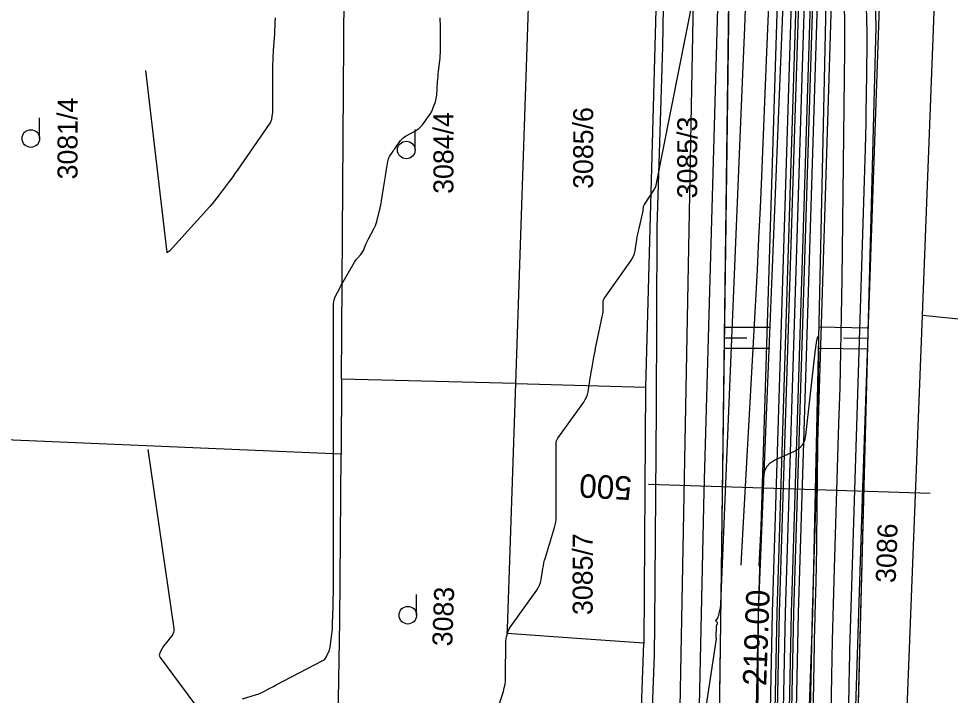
# Model space of a CAD drawing. Extents: x -534410 to -534262, y -1190162 to -1189584.
# Drawn here: x -534356.09 to -534316.44, y -1190081.68 to -1190052.88 of the extents above; entities that cross this region are included whole.
import ezdxf

# ---------------------------------------------------------------- set-up
doc = ezdxf.new("R2010")
doc.units = 0
for name, color, linetype in [('07_ELEKTRO', 7, 'Continuous'), ('30', 7, 'Continuous'), ('31', 7, 'Continuous'), ('40', 7, 'Continuous'), ('_linie', 7, 'Continuous'), ('_N_osa', 7, 'Continuous'), ('_N_tenká', 7, 'Continuous'), ('_N_tenká_velmi', 7, 'Continuous'), ('_N_text', 7, 'Continuous'), ('_přístup', 7, 'Continuous'), ('_tenka', 7, 'Continuous'), ('_velmi_tenka', 7, 'Continuous'), ('Default', 7, 'Continuous'), ('Hranice parcel', 7, 'Continuous'), ('Parcelní čísla', 7, 'Continuous'), ('Značky kultur', 7, 'Continuous')]:
    doc.layers.add(name, color=color, linetype=linetype)

msp = doc.modelspace()

# ---------------------------------------------------------------- linework, layer by layer
at = {"layer": '07_ELEKTRO'}
msp.add_lwpolyline([(-534329.31, -1190087.46), (-534329.03, -1190079.95), (-534329.01, -1190078.66), (-534328.95, -1190069.47), (-534328.91, -1190061.75), (-534328.68, -1190054.09), (-534328.55, -1190046.44), (-534328.261, -1190025.497), (-534332.174, -1190007.081), (-534334.321, -1190004.167), (-534336.852, -1190002.737), (-534339.713, -1190001.803)], dxfattribs=at)
at = {"layer": '30'}
for points in [[(-534321.439, -1190024.07), (-534321.403, -1190024.729), (-534321.16, -1190031.821), (-534321.095, -1190033.569), (-534321.018, -1190035.317), (-534320.93, -1190037.065), (-534320.831, -1190038.812), (-534320.052, -1190051.814), (-534320.024, -1190052.363), (-534320.005, -1190052.912), (-534319.997, -1190053.461), (-534319.998, -1190054.011), (-534320.024, -1190056.21), (-534320.031, -1190056.76), (-534320.042, -1190057.31), (-534320.054, -1190057.86), (-534320.07, -1190058.409), (-534320.726, -1190079.747), (-534320.736, -1190080.069), (-534320.744, -1190080.391), (-534320.751, -1190080.713), (-534320.757, -1190081.035), (-534320.78, -1190082.323)], [(-534328.187, -1190091.169), (-534326.393, -1190079.271), (-534326.393, -1190079.267), (-534326.393, -1190079.263), (-534326.394, -1190079.26), (-534326.395, -1190079.256), (-534326.4, -1190079.241), (-534326.401, -1190079.237), (-534326.402, -1190079.234), (-534326.402, -1190079.23), (-534326.403, -1190079.226), (-534326.385, -1190078.709), (-534326.384, -1190078.703), (-534326.383, -1190078.696), (-534326.381, -1190078.69), (-534326.378, -1190078.684), (-534326.357, -1190078.649), (-534326.355, -1190078.646), (-534326.343, -1190078.602), (-534326.342, -1190078.595), (-534326.343, -1190078.588), (-534326.346, -1190078.582), (-534326.35, -1190078.577), (-534326.405, -1190078.527), (-534326.413, -1190078.517), (-534326.416, -1190078.506), (-534326.414, -1190078.495), (-534326.407, -1190078.484), (-534326.342, -1190078.407), (-534326.34, -1190078.403), (-534326.338, -1190078.4), (-534326.336, -1190078.396), (-534326.335, -1190078.392), (-534326.33, -1190078.372), (-534326.327, -1190078.361), (-534326.321, -1190078.34), (-534326.318, -1190078.33), (-534326.314, -1190078.321), (-534326.301, -1190078.29), (-534326.298, -1190078.283), (-534326.296, -1190078.275), (-534326.291, -1190078.255), (-534326.288, -1190078.243), (-534326.278, -1190078.211), (-534326.276, -1190078.204), (-534326.274, -1190078.197), (-534326.273, -1190078.19), (-534326.271, -1190078.183), (-534326.227, -1190077.952), (-534326.22, -1190077.911), (-534326.214, -1190077.87), (-534326.21, -1190077.829), (-534326.208, -1190077.787), (-534325.27, -1190055.236), (-534325.189, -1190053.257), (-534325.109, -1190051.279)], [(-534346.562, -1190081.825), (-534345.87, -1190081.605), (-534345.807, -1190081.583), (-534345.746, -1190081.559), (-534345.685, -1190081.531), (-534345.626, -1190081.501), (-534345.393, -1190081.375), (-534345.335, -1190081.343), (-534345.276, -1190081.312), (-534345.217, -1190081.281), (-534345.159, -1190081.25), (-534343.147, -1190080.2), (-534343.099, -1190080.171), (-534343.059, -1190080.135), (-534343.024, -1190080.093), (-534342.997, -1190080.045), (-534342.898, -1190079.841), (-534342.875, -1190079.79), (-534342.857, -1190079.737), (-534342.843, -1190079.682), (-534342.834, -1190079.627), (-534342.762, -1190079.068), (-534342.749, -1190078.956), (-534342.739, -1190078.844), (-534342.732, -1190078.732), (-534342.727, -1190078.619), (-534342.708, -1190077.898), (-534342.708, -1190077.88), (-534342.708, -1190077.862), (-534342.708, -1190077.827), (-534342.707, -1190077.809), (-534342.707, -1190077.791), (-534342.689, -1190077.086), (-534342.687, -1190076.965), (-534342.685, -1190076.844), (-534342.683, -1190076.724), (-534342.683, -1190076.603), (-534342.683, -1190065.019), (-534342.678, -1190064.933), (-534342.663, -1190064.849), (-534342.638, -1190064.769), (-534342.602, -1190064.69), (-534342.44, -1190064.382), (-534342.4, -1190064.305), (-534342.358, -1190064.229), (-534342.316, -1190064.153), (-534342.273, -1190064.077), (-534341.796, -1190063.249), (-534341.768, -1190063.204), (-534341.738, -1190063.161), (-534341.706, -1190063.119), (-534341.671, -1190063.079), (-534341.528, -1190062.923), (-534341.494, -1190062.882), (-534341.464, -1190062.839), (-534341.439, -1190062.794), (-534341.417, -1190062.746), (-534341.309, -1190062.482), (-534341.284, -1190062.423), (-534341.257, -1190062.363), (-534341.228, -1190062.305), (-534341.198, -1190062.248), (-534340.985, -1190061.861), (-534340.942, -1190061.777), (-534340.904, -1190061.69), (-534340.873, -1190061.601), (-534340.847, -1190061.51), (-534340.732, -1190061.043), (-534340.709, -1190060.944), (-534340.687, -1190060.844), (-534340.668, -1190060.743), (-534340.65, -1190060.642), (-534340.562, -1190060.092), (-534340.534, -1190059.922), (-534340.479, -1190059.581), (-534340.461, -1190059.467), (-534340.379, -1190058.955), (-534340.367, -1190058.901), (-534340.35, -1190058.849), (-534340.328, -1190058.799), (-534340.3, -1190058.751), (-534340.178, -1190058.564), (-534340.147, -1190058.518), (-534340.116, -1190058.471), (-534340.084, -1190058.425), (-534340.052, -1190058.38), (-534339.837, -1190058.075), (-534339.787, -1190058.012), (-534339.731, -1190057.957), (-534339.668, -1190057.908), (-534339.6, -1190057.867), (-534339.204, -1190057.658), (-534339.118, -1190057.606), (-534339.039, -1190057.546), (-534338.969, -1190057.477), (-534338.905, -1190057.399), (-534338.593, -1190056.966), (-534338.551, -1190056.904), (-534338.515, -1190056.84), (-534338.483, -1190056.773), (-534338.456, -1190056.704), (-534338.356, -1190056.422), (-534338.334, -1190056.351), (-534338.316, -1190056.279), (-534338.304, -1190056.206), (-534338.296, -1190056.133), (-534338.259, -1190055.571), (-534338.251, -1190055.459), (-534338.241, -1190055.346), (-534338.231, -1190055.234), (-534338.218, -1190055.121), (-534338.166, -1190054.672), (-534338.154, -1190054.56), (-534338.146, -1190054.447), (-534338.141, -1190054.335), (-534338.14, -1190054.222), (-534338.14, -1190053.34), (-534338.14, -1190053.291), (-534338.141, -1190053.241), (-534338.141, -1190053.192), (-534338.143, -1190053.142), (-534338.148, -1190052.943), (-534338.149, -1190052.894), (-534338.15, -1190052.845)], [(-534324.582, -1190076.169), (-534324.371, -1190072.338), (-534324.333, -1190072.121), (-534324.245, -1190071.938), (-534324.108, -1190071.789), (-534323.919, -1190071.675), (-534323.067, -1190071.284), (-534322.878, -1190071.169), (-534322.734, -1190071.02), (-534322.638, -1190070.838), (-534322.588, -1190070.622), (-534322.186, -1190067.078), (-534322.121, -1190066.577), (-534322.076, -1190066.412), (-534322.053, -1190066.582), (-534322.05, -1190067.087), (-534322.157, -1190076.409), (-534322.16, -1190076.598), (-534322.163, -1190076.787), (-534322.168, -1190076.975), (-534322.173, -1190077.164), (-534322.196, -1190077.919), (-534322.202, -1190078.108), (-534322.206, -1190078.297), (-534322.211, -1190078.485), (-534322.214, -1190078.674), (-534322.64, -1190103.1)], [(-534350.597, -1190071.215), (-534349.487, -1190078.826), (-534349.483, -1190078.915), (-534349.496, -1190078.999), (-534349.528, -1190079.078), (-534349.577, -1190079.152), (-534349.858, -1190079.496), (-534349.892, -1190079.539), (-534349.923, -1190079.584), (-534349.952, -1190079.631), (-534349.979, -1190079.679), (-534350.082, -1190079.873), (-534350.1, -1190079.921), (-534350.104, -1190079.968), (-534350.093, -1190080.014), (-534350.068, -1190080.059), (-534348.04, -1190082.803)]]:
    msp.add_lwpolyline(points, dxfattribs=at)
at = {"layer": '31'}
for points in [[(-534335.714, -1190082.285), (-534335.462, -1190081.509), (-534335.421, -1190081.363), (-534335.391, -1190081.216), (-534335.372, -1190081.066), (-534335.365, -1190080.915), (-534335.35, -1190079.342), (-534335.348, -1190079.29), (-534335.341, -1190079.24), (-534335.331, -1190079.189), (-534335.316, -1190079.14), (-534335.25, -1190078.943), (-534335.231, -1190078.895), (-534335.21, -1190078.848), (-534335.184, -1190078.803), (-534335.156, -1190078.76), (-534334.039, -1190077.197), (-534333.975, -1190077.095), (-534333.923, -1190076.988), (-534333.885, -1190076.877), (-534333.859, -1190076.759), (-534333.782, -1190076.28), (-534333.76, -1190076.161), (-534333.735, -1190076.042), (-534333.705, -1190075.925), (-534333.672, -1190075.808), (-534333.283, -1190074.54), (-534333.253, -1190074.427), (-534333.231, -1190074.313), (-534333.218, -1190074.197), (-534333.214, -1190074.08), (-534333.214, -1190073.506), (-534333.214, -1190073.374), (-534333.214, -1190073.241), (-534333.214, -1190072.977), (-534333.214, -1190072.911), (-534333.214, -1190072.845), (-534333.214, -1190072.778), (-534333.214, -1190072.712), (-534333.214, -1190072.448), (-534333.214, -1190072.315), (-534333.214, -1190072.183), (-534333.214, -1190071.506), (-534333.214, -1190071.374), (-534333.214, -1190071.241), (-534333.214, -1190070.977), (-534333.21, -1190070.912), (-534333.195, -1190070.851), (-534333.171, -1190070.792), (-534333.138, -1190070.737), (-534332.038, -1190069.196), (-534331.974, -1190069.095), (-534331.923, -1190068.989), (-534331.885, -1190068.877), (-534331.859, -1190068.76), (-534331.782, -1190068.282), (-534331.762, -1190068.162), (-534331.742, -1190068.043), (-534331.721, -1190067.924), (-534331.7, -1190067.804), (-534331.607, -1190067.281), (-534331.583, -1190067.154), (-534331.559, -1190067.027), (-534331.534, -1190066.9), (-534331.508, -1190066.774), (-534331.24, -1190065.505), (-534331.228, -1190065.439), (-534331.22, -1190065.374), (-534331.214, -1190065.308), (-534331.213, -1190065.242), (-534331.213, -1190064.977), (-534331.208, -1190064.912), (-534331.193, -1190064.851), (-534331.169, -1190064.792), (-534331.135, -1190064.737), (-534330.037, -1190063.195), (-534329.974, -1190063.094), (-534329.923, -1190062.988), (-534329.884, -1190062.877), (-534329.859, -1190062.76), (-534329.782, -1190062.284), (-534329.761, -1190062.165), (-534329.739, -1190062.047), (-534329.715, -1190061.928), (-534329.688, -1190061.811), (-534329.528, -1190061.128), (-534329.522, -1190061.1), (-534329.517, -1190061.072), (-534329.512, -1190061.044), (-534329.509, -1190061.016), (-534329.497, -1190060.902), (-534329.493, -1190060.874), (-534329.485, -1190060.847), (-534329.474, -1190060.821), (-534329.46, -1190060.796), (-534329.033, -1190060.14), (-534329.011, -1190060.107), (-534328.99, -1190060.074), (-534328.985, -1190060.065), (-534328.981, -1190060.057), (-534328.977, -1190060.047), (-534328.975, -1190060.038), (-534327.353, -1190051.869)], [(-534325.339, -1190076.14), (-534325.297, -1190075.335), (-534324.723, -1190064.883), (-534324.653, -1190063.563), (-534324.587, -1190062.243), (-534324.526, -1190060.922), (-534324.469, -1190059.601), (-534324.249, -1190054.317), (-534324.195, -1190052.996), (-534324.141, -1190051.675)], [(-534320.964, -1190052.178), (-534320.949, -1190053.183), (-534320.951, -1190054.188), (-534321.064, -1190063.973), (-534321.085, -1190065.511), (-534321.114, -1190067.048), (-534321.15, -1190068.585), (-534321.193, -1190070.122), (-534321.382, -1190076.27), (-534321.427, -1190077.807), (-534321.467, -1190079.344), (-534321.501, -1190080.881), (-534321.531, -1190082.418)], [(-534345.17, -1190052.846), (-534345.178, -1190052.913), (-534345.183, -1190052.981), (-534345.192, -1190053.254), (-534345.195, -1190053.323), (-534345.198, -1190053.391), (-534345.202, -1190053.459), (-534345.206, -1190053.527), (-534345.256, -1190054.246), (-534345.26, -1190054.306), (-534345.263, -1190054.366), (-534345.266, -1190054.426), (-534345.269, -1190054.485), (-534345.277, -1190054.725), (-534345.279, -1190054.785), (-534345.281, -1190054.845), (-534345.281, -1190054.904), (-534345.282, -1190054.964), (-534345.282, -1190056.743), (-534345.283, -1190056.794), (-534345.285, -1190056.844), (-534345.29, -1190056.895), (-534345.296, -1190056.945), (-534345.325, -1190057.147), (-534345.335, -1190057.196), (-534345.351, -1190057.243), (-534345.372, -1190057.288), (-534345.398, -1190057.331), (-534346.793, -1190059.347), (-534346.885, -1190059.479), (-534346.978, -1190059.61), (-534347.072, -1190059.741), (-534347.168, -1190059.87), (-534347.551, -1190060.387), (-534347.649, -1190060.515), (-534347.749, -1190060.64), (-534347.853, -1190060.763), (-534347.959, -1190060.883), (-534349.675, -1190062.776), (-534349.681, -1190062.782), (-534349.687, -1190062.787), (-534349.694, -1190062.792), (-534349.701, -1190062.796), (-534349.74, -1190062.82), (-534349.746, -1190062.824), (-534349.754, -1190062.831), (-534349.757, -1190062.835), (-534349.761, -1190062.843), (-534349.762, -1190062.842), (-534349.762, -1190062.841), (-534350.673, -1190055.087)]]:
    msp.add_lwpolyline(points, dxfattribs=at)
at = {"layer": '_linie'}
for points in [[(-534351.8, -1189951.99), (-534346.88, -1189964.25), (-534328.11, -1190005.55), (-534325.796, -1190021.686), (-534325.86, -1190050.97), (-534326.22, -1190078.56), (-534326.79, -1190120.4), (-534329.12, -1190134.93), (-534323.49, -1190133.89), (-534321.38, -1190121.46), (-534319.59, -1190053.22), (-534320.45, -1190021.195), (-534322.75, -1190003.33), (-534340.65, -1189960.04), (-534344.52, -1189948.89)], [(-534347.45, -1189950.137), (-534345.54, -1189954.54), (-534325.02, -1190005.35), (-534322.054, -1190021.393), (-534321.72, -1190051.56), (-534322.31, -1190078.15), (-534323.81, -1190120.37), (-534326.521, -1190134.45)], [(-534328.194, -1190134.759), (-534324.85, -1190120.45), (-534324.6, -1190078.17), (-534323.54, -1190051.92), (-534323.273, -1190021.516), (-534325.81, -1190005.43), (-534346.66, -1189954.59), (-534348.342, -1189950.518)]]:
    msp.add_lwpolyline(points, dxfattribs=at)
at = {"layer": '_N_osa'}
msp.add_lwpolyline([(-534327.357, -1190134.604), (-534324.33, -1190120.41), (-534323.455, -1190078.16), (-534322.63, -1190051.74), (-534322.663, -1190021.455), (-534325.415, -1190005.39), (-534346.1, -1189954.565), (-534347.892, -1189950.326)], dxfattribs=at)
at = {"layer": '_N_tenká'}
for points in [[(-534326.133, -1190134.378), (-534323.183, -1190120.543), (-534322.305, -1190078.19), (-534321.48, -1190051.757), (-534321.513, -1190021.356), (-534324.303, -1190005.072), (-534345.038, -1189954.124), (-534346.832, -1189949.878)], [(-534327.091, -1190134.555), (-534324.081, -1190120.439), (-534323.205, -1190078.166), (-534322.38, -1190051.744), (-534322.413, -1190021.433), (-534325.173, -1190005.321), (-534345.869, -1189954.469), (-534347.661, -1189950.228)], [(-534328.581, -1190134.83), (-534325.477, -1190120.277), (-534324.605, -1190078.13), (-534323.78, -1190051.723), (-534323.813, -1190021.553), (-534326.527, -1190005.708), (-534347.162, -1189955.006), (-534348.951, -1189950.773)], [(-534327.623, -1190134.654), (-534324.579, -1190120.381), (-534323.705, -1190078.154), (-534322.88, -1190051.736), (-534322.913, -1190021.476), (-534325.657, -1190005.459), (-534346.331, -1189954.661), (-534348.122, -1189950.423)]]:
    msp.add_lwpolyline(points, dxfattribs=at)
at = {"layer": '_N_tenká_velmi'}
for points in [[(-534326.985, -1190134.536), (-534323.981, -1190120.45), (-534323.105, -1190078.169), (-534322.28, -1190051.745), (-534322.313, -1190021.425), (-534325.076, -1190005.293), (-534345.777, -1189954.431), (-534347.569, -1189950.189)], [(-534326.772, -1190134.496), (-534323.781, -1190120.474), (-534322.905, -1190078.174), (-534322.08, -1190051.748), (-534322.113, -1190021.407), (-534324.883, -1190005.238), (-534345.592, -1189954.354), (-534347.385, -1189950.112)], [(-534327.943, -1190134.713), (-534324.879, -1190120.346), (-534324.005, -1190078.146), (-534323.18, -1190051.732), (-534323.213, -1190021.502), (-534325.947, -1190005.542), (-534346.608, -1189954.776), (-534348.398, -1189950.54)], [(-534327.73, -1190134.673), (-534324.679, -1190120.37), (-534323.805, -1190078.151), (-534322.98, -1190051.735), (-534323.013, -1190021.485), (-534325.754, -1190005.487), (-534346.423, -1189954.699), (-534348.214, -1189950.462)]]:
    msp.add_lwpolyline(points, dxfattribs=at)
at = {"layer": '_N_text'}
msp.add_lwpolyline([(-534317.294, -1190073.085), (-534329.288, -1190072.711)], dxfattribs=at)
at = {"layer": '_přístup'}
msp.add_lwpolyline([(-534330.552, -1190135.191), (-534328.648, -1190119.819), (-534326.845, -1190024.247), (-534332.805, -1189999.297), (-534354.454, -1189948.317)], dxfattribs=at)
at = {"layer": '_tenka'}
for points in [[(-534351.8, -1189951.99), (-534346.88, -1189964.25), (-534328.11, -1190005.55), (-534325.796, -1190021.686), (-534325.86, -1190050.97), (-534326.22, -1190078.56), (-534326.79, -1190120.4), (-534329.12, -1190134.93), (-534323.49, -1190133.89), (-534321.38, -1190121.46), (-534319.59, -1190053.22), (-534320.45, -1190021.195), (-534322.75, -1190003.33), (-534340.65, -1189960.04), (-534344.52, -1189948.89)], [(-534327.55, -1190134.64), (-534323.49, -1190133.89), (-534321.38, -1190121.46), (-534319.59, -1190053.22), (-534320.45, -1190021.195), (-534322.75, -1190003.33), (-534340.65, -1189960.04), (-534344.52, -1189948.89)], [(-534347.45, -1189950.137), (-534345.54, -1189954.54), (-534325.02, -1190005.35), (-534322.054, -1190021.393), (-534321.72, -1190051.56), (-534322.31, -1190078.15), (-534323.81, -1190120.37), (-534326.521, -1190134.45)], [(-534347.45, -1189950.137), (-534345.54, -1189954.54), (-534325.02, -1190005.35), (-534322.054, -1190021.393), (-534321.72, -1190051.56), (-534322.31, -1190078.15), (-534323.81, -1190120.37), (-534326.521, -1190134.45)], [(-534328.194, -1190134.759), (-534324.85, -1190120.45), (-534324.6, -1190078.17), (-534323.54, -1190051.92), (-534323.273, -1190021.516), (-534325.81, -1190005.43), (-534346.66, -1189954.59), (-534348.342, -1189950.518)], [(-534328.194, -1190134.759), (-534324.85, -1190120.45), (-534324.6, -1190078.17), (-534323.54, -1190051.92), (-534323.273, -1190021.516), (-534325.81, -1190005.43), (-534346.66, -1189954.59), (-534348.342, -1189950.518)], [(-534351.8, -1189951.99), (-534346.88, -1189964.25), (-534328.11, -1190005.55), (-534325.796, -1190021.686), (-534325.86, -1190050.97), (-534326.22, -1190078.56), (-534326.79, -1190120.4), (-534329.12, -1190134.93), (-534327.55, -1190134.64)]]:
    msp.add_lwpolyline(points, dxfattribs=at)
at = {"layer": '_velmi_tenka'}
for p, q in [((-534326.063, -1190066.011), (-534324.128, -1190066.008)), ((-534319.931, -1190066.048), (-534322.043, -1190066.012)), ((-534326.062, -1190066.461), (-534325.095, -1190066.459)), ((-534319.938, -1190066.498), (-534320.994, -1190066.48)), ((-534326.061, -1190066.911), (-534324.126, -1190066.908)), ((-534319.946, -1190066.948), (-534322.058, -1190066.912))]:
    msp.add_line(p, q, dxfattribs=at)
at = {"layer": 'Default'}
for p, q in [((-534325.86, -1190050.97), (-534326.22, -1190078.56)), ((-534321.38, -1190121.46), (-534319.59, -1190053.22)), ((-534326.22, -1190078.56), (-534326.79, -1190120.4))]:
    msp.add_line(p, q, dxfattribs=at)
msp.add_lwpolyline([(-534319.59, -1190053.22), (-534320.45, -1190021.195), (-534322.75, -1190003.33)], dxfattribs=at)
at = {"layer": 'Hranice parcel'}
for p, q in [((-534334.93, -1190068.41), (-534334.16, -1190045.57)), ((-534328.79, -1190045.66), (-534329.41, -1190068.56)), ((-534318.39, -1190085.1), (-534317.63, -1190065.52)), ((-534307.49, -1190066.49), (-534317.63, -1190065.52)), ((-534342.35, -1190068.22), (-534342.37, -1190071.42)), ((-534334.93, -1190068.41), (-534342.35, -1190068.22)), ((-534334.93, -1190068.41), (-534329.41, -1190068.56)), ((-534329.41, -1190068.56), (-534329.49, -1190079.46)), ((-534342.37, -1190071.42), (-534367.49, -1190070.35)), ((-534329.74, -1190087.07), (-534329.49, -1190079.46))]:
    msp.add_line(p, q, dxfattribs=at)
for points in [[(-534333.99, -1189993.03), (-534331.98, -1189997.67), (-534327.34, -1190013.08), (-534325.48, -1190021.81), (-534326.93, -1190073), (-534328.13, -1190128.3), (-534328.71, -1190131.86)], [(-534322.11, -1190134.26), (-534321.95, -1190128.7), (-534320.16, -1190072.85), (-534318.8, -1190033.53)], [(-534317.63, -1190065.52), (-534317.11, -1190052.22), (-534318.8, -1190033.53)], [(-534342.35, -1190068.22), (-534342.22, -1190049.76), (-534342.19, -1190045.44)], [(-534329.49, -1190079.46), (-534332.14, -1190079.27), (-534335.3, -1190079.04), (-534335.29, -1190078.85), (-534334.93, -1190068.41)], [(-534342.57, -1190087.3), (-534342.5, -1190083.48), (-534342.42, -1190078.52), (-534342.37, -1190071.42)]]:
    msp.add_lwpolyline(points, dxfattribs=at)
at = {"layer": 'Značky kultur'}
for p, q in [((-534355.195, -1190057.985), (-534355.195, -1190057.11)), ((-534339.217, -1190058.472), (-534339.217, -1190057.597)), ((-534339.152, -1190078.266), (-534339.152, -1190077.391))]:
    msp.add_line(p, q, dxfattribs=at)
for centre in [(-534355.57, -1190057.985), (-534339.592, -1190058.472), (-534339.527, -1190078.266)]:
    msp.add_circle(centre, 0.375, dxfattribs=at)

# ---------------------------------------------------------------- texts
at = {"layer": '40'}
msp.add_text('219.00', height=1, rotation=87.8077, dxfattribs=at).set_placement((-534324.277, -1190081.286))
at = {"layer": '_N_text'}
msp.add_text('500', height=1, rotation=176.9849, dxfattribs=at).set_placement((-534329.973, -1190072.372))
at = {"layer": 'Parcelní čísla'}
for s, rotation, p in [('3081/4', 90, (-534353.583, -1190059.724)), ('3084/4', 90, (-534337.587, -1190060.338)), ('3085/6', 90, (-534331.639, -1190060.127)), ('3085/3', 90, (-534327.212, -1190060.53)), ('3086', 88, (-534318.768, -1190076.904)), ('3085/7', 90, (-534331.662, -1190078.258)), ('3083', 88, (-534337.639, -1190079.599))]:
    msp.add_text(s, height=0.85, rotation=rotation, dxfattribs=at).set_placement(p)

doc.saveas('drawing.dxf')
